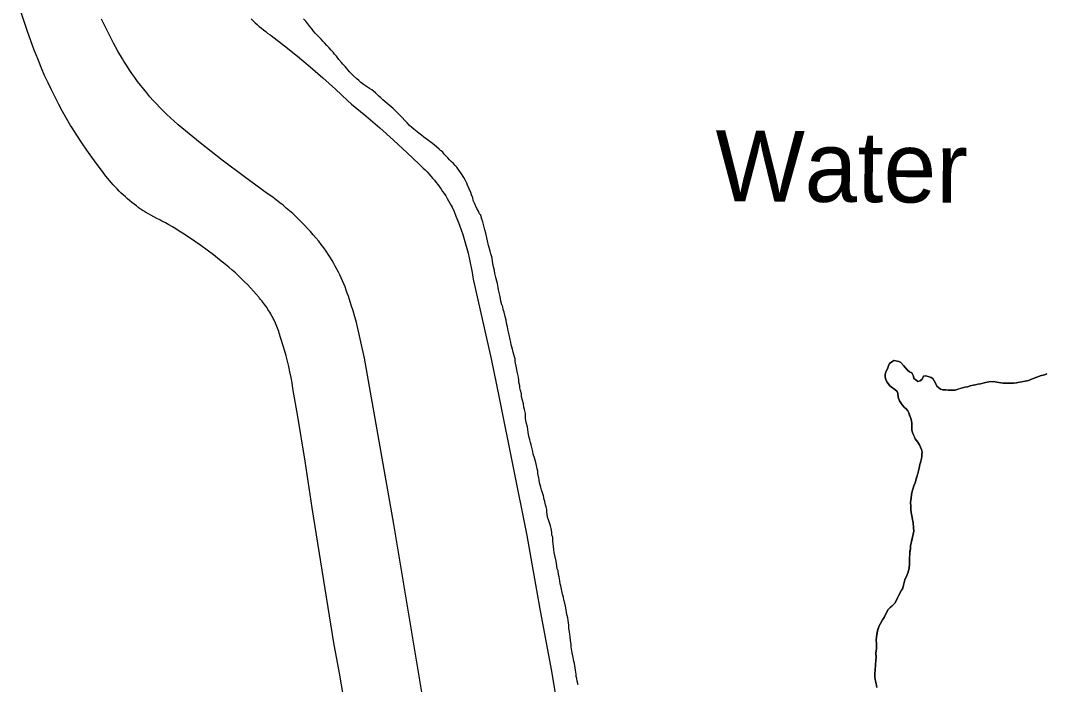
# Model space of a CAD drawing. Extents: x 3172297 to 3210190, y 958463 to 983887.
# Drawn here: x 3188661 to 3190110, y 970542 to 971480 of the extents above; entities that cross this region are included whole.
import ezdxf

# ---------------------------------------------------------------- set-up
doc = ezdxf.new("R2010")
doc.units = 0
for name, color, linetype in [('V-LEVE-TOET', 7, 'Continuous'), ('V-RIVR-IDEN', 7, 'Continuous'), ('V-ROAD-CNTR', 7, 'Continuous'), ('V-SITE-VEGE', 7, 'Continuous'), ('V-TOPO-SHOR', 7, 'Continuous')]:
    doc.layers.add(name, color=color, linetype=linetype)

msp = doc.modelspace()

# ---------------------------------------------------------------- linework, layer by layer
at = {"layer": 'V-LEVE-TOET'}
for points in [[(3188950.3, 971135.2), (3188950.3, 971135.2), (3188941.8, 971142.1), (3188933.1, 971148.9), (3188924.3, 971155.5), (3188915.4, 971162), (3188906.4, 971168.3), (3188897.3, 971174.4), (3188889.3, 971179.6), (3188889.3, 971179.6), (3188884.5, 971182.7), (3188879.8, 971185.6), (3188875, 971188.5), (3188870.1, 971191.3), (3188865.2, 971194.1), (3188860.3, 971196.8), (3188857.3, 971198.4), (3188857.3, 971198.4), (3188853.1, 971200.6), (3188848.9, 971202.8), (3188844.8, 971205.1), (3188841.5, 971207), (3188841.5, 971207), (3188840.1, 971207.6), (3188838.8, 971208.3), (3188837.5, 971209), (3188836.2, 971209.8), (3188835, 971210.6), (3188833.7, 971211.3), (3188832.4, 971212.1), (3188831.2, 971213), (3188830, 971213.8), (3188828.8, 971214.7), (3188827.6, 971215.6), (3188826.4, 971216.5), (3188825.2, 971217.4), (3188824.2, 971218.2), (3188824.2, 971218.2), (3188821, 971220.7), (3188817.9, 971223.2), (3188814.7, 971225.7), (3188811.7, 971228.3), (3188808.7, 971230.9), (3188805.7, 971233.7), (3188802.8, 971236.4), (3188799.9, 971239.2), (3188797.1, 971242.1), (3188794.3, 971245), (3188791.5, 971247.9), (3188788.9, 971250.9), (3188786.2, 971254), (3188783.7, 971257.1), (3188781.2, 971260.2), (3188778.7, 971263.4), (3188776.3, 971266.6), (3188776.2, 971266.7), (3188776.2, 971266.7), (3188768.7, 971276.7), (3188761.3, 971286.9), (3188754.1, 971297.1), (3188747, 971307.5), (3188740.1, 971318), (3188733.4, 971328.6), (3188731.3, 971332), (3188731.3, 971332), (3188725.6, 971341.8), (3188720, 971351.7), (3188714.6, 971361.7), (3188709.3, 971371.8), (3188704.2, 971382), (3188699.4, 971392.2), (3188694.6, 971402.6), (3188690.1, 971413), (3188685.8, 971423.5), (3188681.6, 971434.1), (3188680, 971438.3), (3188680, 971438.3), (3188670, 971466.2), (3188660.6, 971494.4)], [(3188986.2, 971482.4), (3188989, 971479.6), (3188991.9, 971477), (3188994.8, 971474.4), (3188997.7, 971471.8), (3189000.8, 971469.3), (3189003.8, 971466.8), (3189006.9, 971464.4), (3189010, 971462), (3189013.2, 971459.7), (3189014.5, 971458.8), (3189014.5, 971458.8), (3189033.2, 971444.3), (3189051.6, 971429.6), (3189069.8, 971414.5), (3189087.6, 971399.1), (3189105.3, 971383.3), (3189122.6, 971367.3), (3189128.1, 971362.1), (3189128.1, 971362.1), (3189148.2, 971345.4), (3189168.1, 971328.3), (3189187.6, 971310.9), (3189206.9, 971293.1), (3189223.6, 971277.2), (3189223.6, 971277.2), (3189226.5, 971274.5), (3189229.3, 971271.7), (3189232, 971269), (3189234.7, 971266.1), (3189237.4, 971263.3), (3189240, 971260.4), (3189242.6, 971257.4), (3189245.1, 971254.4), (3189247.5, 971251.3), (3189249.9, 971248.2), (3189252.3, 971245.1), (3189254.6, 971241.9), (3189256.8, 971238.7), (3189259, 971235.5), (3189261.1, 971232.2), (3189263.2, 971228.8), (3189265.2, 971225.5), (3189267.1, 971222.1), (3189269, 971218.7), (3189270.2, 971216.4), (3189270.2, 971216.4), (3189273, 971210.1), (3189275.6, 971203.7), (3189278.1, 971197.3), (3189280.6, 971190.8), (3189282.9, 971184.3), (3189285.1, 971177.8), (3189287.2, 971171.2), (3189289.1, 971164.6), (3189291, 971158), (3189292.7, 971151.3)], [(3189292.7, 971151.3), (3189294.3, 971144.6), (3189295.8, 971137.9), (3189297.2, 971131.1), (3189298.5, 971124.3), (3189299.6, 971117.5), (3189300, 971114.8), (3189300, 971114.8), (3189325.1, 971002.3), (3189336.7, 970947.2), (3189336.7, 970947.2), (3189375.9, 970752.6), (3189375.9, 970752.6), (3189393.5, 970651.1), (3189410.2, 970562.9), (3189410.2, 970562.9), (3189444.3, 970359.5)], [(3189125, 970475.7), (3189111, 970557.8), (3189103.1, 970600.6), (3189103.1, 970600.6), (3189072.6, 970791.6), (3189072.6, 970791.6), (3189062.8, 970857.5), (3189051.8, 970923.2), (3189046.6, 970952.3), (3189046.6, 970952.3), (3189045.4, 970960.2), (3189044.1, 970968), (3189042.7, 970975.7), (3189041.1, 970983.5), (3189039.4, 970991.2), (3189037.6, 970998.9), (3189035.6, 971006.5), (3189033.5, 971014.2), (3189031.2, 971021.7), (3189028.9, 971029.3), (3189027.4, 971033.7), (3189027.4, 971033.7), (3189026.7, 971036.1), (3189026, 971038.5), (3189025.2, 971040.8), (3189024.4, 971043.2), (3189023.5, 971045.5), (3189022.6, 971047.8), (3189021.6, 971050.1), (3189020.7, 971052.4), (3189019.6, 971054.7), (3189018.6, 971056.9), (3189017.5, 971059.1), (3189016.3, 971061.3), (3189015.1, 971063.5), (3189013.9, 971065.7), (3189012.7, 971067.8), (3189011.4, 971069.9), (3189010, 971072), (3189008.7, 971074.1), (3189007.3, 971076.2), (3189005.8, 971078.2), (3189004.4, 971080.2), (3189002.9, 971082.2), (3189001.3, 971084.1), (3188999.7, 971086), (3188998.1, 971087.9), (3188997.5, 971088.7), (3188997.5, 971088.7), (3188993.6, 971093.3), (3188989.6, 971097.8), (3188985.5, 971102.3), (3188981.4, 971106.6), (3188977.1, 971111), (3188972.8, 971115.2), (3188968.5, 971119.4), (3188964, 971123.4), (3188959.5, 971127.5), (3188954.9, 971131.4), (3188950.3, 971135.2)]]:
    msp.add_lwpolyline(points, dxfattribs=at)
at = {"layer": 'V-ROAD-CNTR'}
for points in [[(3189146.3, 971003), (3189135.3, 971053.3), (3189132.9, 971061.6), (3189130.4, 971069.8), (3189127.8, 971078), (3189125, 971086.1), (3189125, 971086.1), (3189123.6, 971090.5), (3189122.1, 971094.9), (3189120.5, 971099.2), (3189118.9, 971103.6), (3189117.1, 971107.9), (3189115.3, 971112.1), (3189113.5, 971116.4), (3189111.5, 971120.6), (3189109.5, 971124.7), (3189107.4, 971128.9), (3189105.2, 971133), (3189103, 971137), (3189100.7, 971141), (3189098.3, 971145), (3189095.8, 971148.9), (3189093.3, 971152.8), (3189092.5, 971154), (3189092.5, 971154), (3189089, 971158.8), (3189085.4, 971163.6), (3189081.7, 971168.3), (3189077.9, 971172.9), (3189074.1, 971177.4), (3189070.1, 971181.9), (3189066.1, 971186.3), (3189062.1, 971190.7), (3189057.9, 971194.9), (3189053.7, 971199.1), (3189049.4, 971203.2), (3189045, 971207.3), (3189040.5, 971211.3), (3189036, 971215.2), (3189031.4, 971219), (3189026.8, 971222.7), (3189022.1, 971226.3), (3189017.3, 971229.9), (3189012.5, 971233.4), (3189009.1, 971235.7), (3189009.1, 971235.7), (3188977.1, 971259.1), (3188945.4, 971283), (3188914.2, 971307.5), (3188883.4, 971332.5), (3188882.6, 971333.2), (3188877.4, 971337.8), (3188872.3, 971342.5), (3188867.3, 971347.3), (3188862.3, 971352.2), (3188857.5, 971357.1), (3188852.7, 971362.2), (3188848, 971367.3), (3188843.4, 971372.5), (3188839, 971377.8), (3188834.6, 971383.2), (3188830.2, 971388.6), (3188826, 971394.1), (3188821.9, 971399.7), (3188817.9, 971405.4), (3188814, 971411.1), (3188810.2, 971416.9), (3188806.5, 971422.8), (3188804.5, 971425.9), (3188804.5, 971425.9), (3188798.2, 971437), (3188792.1, 971448.1), (3188786.1, 971459.4), (3188780.4, 971470.8), (3188774.8, 971482.2)], [(3189387, 969592.5), (3189378.6, 969645.9), (3189378.6, 969645.9), (3189335.3, 969888.2), (3189305.1, 970072.7), (3189305.1, 970072.7), (3189239.6, 970457.8), (3189239.6, 970457.8), (3189188, 970768.6), (3189188, 970768.6), (3189146.3, 971003)]]:
    msp.add_lwpolyline(points, dxfattribs=at)
at = {"layer": 'V-SITE-VEGE'}
for p, q in [((3189888, 970995.6), (3189886.4, 970992)), ((3189891.3, 970997.9), (3189888, 970995.6)), ((3189894, 970999.7), (3189891.3, 970997.9)), ((3189901.2, 970998.4), (3189894, 970999.7)), ((3189903.9, 970996.9), (3189901.2, 970998.4)), ((3189907.5, 970992.7), (3189903.9, 970996.9)), ((3189882.8, 970983.9), (3189881.8, 970980)), ((3189881.8, 970980), (3189881.8, 970976.1)), ((3189885.2, 970987.8), (3189882.8, 970983.9)), ((3189886.4, 970992), (3189885.2, 970987.8)), ((3189910.4, 970989.6), (3189907.5, 970992.7)), ((3189913.4, 970986.3), (3189910.4, 970989.6)), ((3189916.4, 970983.8), (3189913.4, 970986.3)), ((3189919.4, 970982.3), (3189916.4, 970983.8)), ((3189922, 970977.5), (3189919.4, 970982.3)), ((3190110.4, 970980.8), (3190106.7, 970979.6)), ((3189881.8, 970976.1), (3189882.6, 970973.1)), ((3189882.6, 970973.1), (3189884.1, 970969.5)), ((3189884.1, 970969.5), (3189885.9, 970967.1)), ((3189885.9, 970967.1), (3189888.5, 970963.7)), ((3189922.3, 970974.5), (3189922, 970977.5)), ((3189925, 970972.6), (3189922.3, 970974.5)), ((3189928.2, 970970.2), (3189925, 970972.6)), ((3189931.3, 970970.8), (3189928.2, 970970.2)), ((3189934.3, 970973.4), (3189931.3, 970970.8)), ((3189936.1, 970977.6), (3189934.3, 970973.4)), ((3189939.4, 970977.9), (3189936.1, 970977.6)), ((3189942.7, 970977.2), (3189939.4, 970977.9)), ((3189946.6, 970975.7), (3189942.7, 970977.2)), ((3189949.3, 970974.2), (3189946.6, 970975.7)), ((3189952.8, 970967.5), (3189949.3, 970974.2)), ((3189954.6, 970963.3), (3189952.8, 970967.5)), ((3190009.3, 970965.4), (3190006, 970964.8)), ((3190012.6, 970966.3), (3190009.3, 970965.4)), ((3190016.5, 970966.8), (3190012.6, 970966.3)), ((3190023.4, 970968.5), (3190016.5, 970966.8)), ((3190031.2, 970970), (3190023.4, 970968.5)), ((3190034, 970969.6), (3190031.2, 970970)), ((3190034.9, 970969.9), (3190034, 970969.6)), ((3190039.7, 970969.3), (3190034.9, 970969.9)), ((3190045, 970968), (3190039.7, 970969.3)), ((3190048.3, 970967.7), (3190045, 970968)), ((3190063.1, 970967.5), (3190048.3, 970967.7)), ((3190067.3, 970968), (3190063.1, 970967.5)), ((3190079.6, 970970.3), (3190067.3, 970968)), ((3190084.4, 970971.5), (3190079.6, 970970.3)), ((3190090.8, 970974.4), (3190084.4, 970971.5)), ((3190097.7, 970976.7), (3190090.8, 970974.4)), ((3190101, 970978.2), (3190097.7, 970976.7)), ((3190106.7, 970979.6), (3190101, 970978.2)), ((3189888.5, 970963.7), (3189895.4, 970958.9)), ((3189895.4, 970958.9), (3189898.7, 970956.1)), ((3189898.7, 970956.1), (3189899.5, 970953.1)), ((3189899.5, 970953.1), (3189900.1, 970947.7)), ((3189960, 970959.3), (3189954.6, 970963.3)), ((3189963.3, 970958.4), (3189960, 970959.3)), ((3189967.5, 970958.4), (3189963.3, 970958.4)), ((3189971, 970957.7), (3189967.5, 970958.4)), ((3189977.7, 970957.9), (3189971, 970957.7)), ((3189980.7, 970957.9), (3189977.7, 970957.9)), ((3189990.9, 970961.1), (3189980.7, 970957.9)), ((3189994.5, 970962), (3189990.9, 970961.1)), ((3189998.1, 970962.5), (3189994.5, 970962)), ((3190002.1, 970964), (3189998.1, 970962.5)), ((3190006, 970964.8), (3190002.1, 970964)), ((3189900.1, 970947.7), (3189902.1, 970942.9)), ((3189902.1, 970942.9), (3189905.7, 970937.1)), ((3189905.7, 970937.1), (3189909.2, 970933.2)), ((3189909.2, 970933.2), (3189911.6, 970931.3)), ((3189911.6, 970931.3), (3189913.7, 970928.6)), ((3189913.7, 970928.6), (3189915.1, 970925.6)), ((3189915.1, 970925.6), (3189918.6, 970916.3)), ((3189918.6, 970916.3), (3189919.5, 970911.7)), ((3189919.5, 970911.7), (3189919.7, 970908.4)), ((3189919.7, 970908.4), (3189919.7, 970901.2)), ((3189919.7, 970901.2), (3189921.1, 970896.4)), ((3189921.1, 970896.4), (3189924, 970889.2)), ((3189924, 970889.2), (3189928.2, 970884.3)), ((3189928.2, 970884.3), (3189930.2, 970880.7)), ((3189930.2, 970880.7), (3189933.2, 970874.1)), ((3189933.4, 970864.1), (3189933, 970861.1)), ((3189933.2, 970874.1), (3189934, 970870.1)), ((3189934, 970870.1), (3189933.4, 970867.1)), ((3189933.4, 970867.1), (3189933.4, 970864.1)), ((3189930.2, 970849.8), (3189929.9, 970847.7)), ((3189930.5, 970850.7), (3189930.2, 970849.8)), ((3189931.2, 970854.2), (3189930.5, 970850.7)), ((3189933, 970861.1), (3189931.2, 970854.2)), ((3189928.9, 970843.8), (3189924.2, 970827)), ((3189929.9, 970847.7), (3189928.9, 970843.8)), ((3189922.4, 970822.5), (3189919.9, 970814.4)), ((3189924.2, 970827), (3189922.4, 970822.5)), ((3189918.9, 970810.2), (3189918.6, 970805.1)), ((3189919.9, 970814.4), (3189918.9, 970810.2)), ((3189918.6, 970805.1), (3189917.6, 970799.1)), ((3189917.6, 970799.1), (3189918.2, 970793.7)), ((3189918.2, 970793.7), (3189918.1, 970789.2)), ((3189918.1, 970789.2), (3189918.4, 970785)), ((3189918.4, 970785), (3189921.2, 970770.3)), ((3189921.2, 970770.3), (3189921.7, 970763.7)), ((3189921.7, 970763.7), (3189922.3, 970758.8)), ((3189922.3, 970758.8), (3189919.1, 970743.6)), ((3189919.1, 970743.6), (3189917.5, 970738.5)), ((3189917.5, 970738.5), (3189917.5, 970733.4)), ((3189916.4, 970719.9), (3189916.1, 970715.1)), ((3189916.5, 970728.6), (3189916.4, 970719.9)), ((3189917.5, 970733.4), (3189916.5, 970728.6)), ((3189915.7, 970706.7), (3189914.1, 970700.4)), ((3189916, 970712.1), (3189915.7, 970706.7)), ((3189916.1, 970715.1), (3189916, 970712.1)), ((3189912.6, 970695.9), (3189909.8, 970689.9)), ((3189914.1, 970700.4), (3189912.6, 970695.9)), ((3189906.7, 970677.9), (3189904.8, 970675.3)), ((3189907.6, 970682.1), (3189906.7, 970677.9)), ((3189908.9, 970686), (3189907.6, 970682.1)), ((3189909.8, 970689.9), (3189908.9, 970686)), ((3189899.3, 970664.2), (3189895.9, 970657.3)), ((3189899.6, 970665.1), (3189899.3, 970664.2)), ((3189900.8, 970667.2), (3189899.6, 970665.1)), ((3189904.8, 970675.3), (3189900.8, 970667.2)), ((3189885.6, 970647.2), (3189880.4, 970636.5)), ((3189888.9, 970650.5), (3189885.6, 970647.2)), ((3189891.4, 970652.6), (3189888.9, 970650.5)), ((3189893.8, 970655), (3189891.4, 970652.6)), ((3189895.9, 970657.3), (3189893.8, 970655)), ((3189878.2, 970633.2), (3189875.2, 970628.1)), ((3189880.4, 970636.5), (3189878.2, 970633.2)), ((3189870.8, 970617.7), (3189869.5, 970608.7)), ((3189873.3, 970624.6), (3189870.8, 970617.7)), ((3189875.2, 970628.1), (3189873.3, 970624.6)), ((3189869.5, 970608.7), (3189869.2, 970604.5)), ((3189869.2, 970604.5), (3189869.7, 970600)), ((3189869.4, 970592.8), (3189868.7, 970586.2)), ((3189869.7, 970600), (3189869.4, 970592.8)), ((3189868.6, 970576.9), (3189868.2, 970569.4)), ((3189868.9, 970579.9), (3189868.6, 970576.9)), ((3189868.7, 970586.2), (3189868.9, 970579.9)), ((3189867.5, 970562.5), (3189867.2, 970556.8)), ((3189868.2, 970569.4), (3189867.5, 970562.5)), ((3189867.2, 970556.8), (3189867.4, 970552.2)), ((3189867.4, 970552.2), (3189868, 970546.8)), ((3189868, 970546.8), (3189869.1, 970543.2)), ((3189869.1, 970543.2), (3189870.3, 970537.8))]:
    msp.add_line(p, q, dxfattribs=at)
at = {"layer": 'V-TOPO-SHOR'}
for points in [[(3189074.4, 971465.1), (3189072.3, 971467.8), (3189069.3, 971471.7), (3189066.4, 971475.4), (3189063.4, 971479), (3189060.1, 971482.3)], [(3189325.8, 971147.5), (3189324.9, 971150.5), (3189323.8, 971154.2), (3189322.3, 971159.3), (3189321.7, 971162.3), (3189320.3, 971168.9), (3189319.2, 971173.1), (3189317.7, 971179.7), (3189316.6, 971184.6), (3189315.4, 971188.2), (3189314.3, 971192.1), (3189313.4, 971195.7), (3189312, 971199.6), (3189310.5, 971204.5), (3189310.5, 971205.1), (3189309, 971207.2), (3189307.3, 971210.8), (3189305.2, 971214.7), (3189302, 971222), (3189299.9, 971225.9), (3189299.4, 971229.5), (3189297.6, 971233.7), (3189296.5, 971237), (3189294.4, 971242.5), (3189292.1, 971247.6), (3189290.9, 971250.3), (3189290.3, 971251.2), (3189288.5, 971254.8), (3189286.5, 971258.2), (3189283.2, 971263.6), (3189281.2, 971266.6), (3189278.5, 971270.3), (3189276.7, 971273), (3189274.4, 971275.4), (3189272, 971277.9), (3189269, 971280.9), (3189266.3, 971283.3), (3189264, 971286.1), (3189261.3, 971288.8), (3189258.9, 971291.2), (3189257.1, 971293.9), (3189254.8, 971295.8), (3189253.6, 971296.7), (3189252.1, 971298.2), (3189248.2, 971301.8), (3189245.5, 971304), (3189242.3, 971306.4), (3189239.3, 971308.6), (3189236.6, 971310.7), (3189233.6, 971312.8), (3189230.4, 971315.3), (3189226.8, 971318), (3189223.2, 971321), (3189216.1, 971326.5), (3189213.4, 971329), (3189210.1, 971331.7), (3189206.6, 971335.6), (3189203.3, 971339), (3189199.4, 971343.2), (3189196.2, 971346.3), (3189193.5, 971349), (3189190.2, 971352.3), (3189187, 971355.7), (3189184.3, 971358.1), (3189181.3, 971360.6), (3189178.3, 971362.7), (3189172.1, 971368.2), (3189169.4, 971370.9), (3189166.7, 971373.3), (3189164.4, 971375.5), (3189162, 971377.9), (3189159.3, 971380.3), (3189156.9, 971382.2), (3189153.3, 971384.3), (3189150.7, 971386.1), (3189147.7, 971388), (3189145, 971389.8), (3189141.4, 971392.5), (3189138.2, 971395.6), (3189135.5, 971397.7), (3189130.7, 971402), (3189128.3, 971404.4), (3189125.4, 971407.4), (3189123.3, 971410.2), (3189120.9, 971412.6), (3189118.9, 971415), (3189115.6, 971418.4), (3189113.8, 971420.8), (3189110.3, 971425), (3189106.7, 971429.6), (3189104, 971432.6), (3189102, 971435.3), (3189099.3, 971438.1), (3189096.3, 971441.4), (3189093.4, 971445), (3189090.1, 971448.4), (3189087.4, 971451.1), (3189085.1, 971453.8), (3189080, 971459), (3189076.7, 971462.3), (3189074.4, 971465.1)], [(3189419.9, 970702.3), (3189418.7, 970705.3), (3189418.2, 970709.8), (3189417.6, 970713.1), (3189417.1, 970716.2), (3189415.4, 970724.3), (3189414.5, 970728.2), (3189413.9, 970732.4), (3189413.4, 970737.5), (3189412.6, 970744.4), (3189412.3, 970749.5), (3189411.2, 970753.2), (3189410.9, 970757.1), (3189410.1, 970762.5), (3189408.9, 970766.1), (3189406.3, 970774.8), (3189405.1, 970778.4), (3189404, 970786.3), (3189403.8, 970789.3), (3189403.2, 970792.9), (3189402.3, 970795.9), (3189401.2, 970800.4), (3189400.3, 970803.4), (3189399.2, 970808.5), (3189398, 970812.5), (3189396.6, 970817), (3189395.4, 970820.6), (3189393.7, 970826.9), (3189393.1, 970831.1), (3189392.6, 970834.1), (3189391.1, 970840.2), (3189391.1, 970841.7), (3189391.2, 970843.5), (3189390.3, 970846.8), (3189389.4, 970851.3), (3189388.3, 970855.8), (3189387.4, 970858.8), (3189386.3, 970862.4), (3189384.8, 970867.6), (3189384, 970871.2), (3189382.8, 970876.9), (3189381.7, 970880.5), (3189381.1, 970883.8), (3189379.9, 970887.7), (3189378.8, 970890.8), (3189377.9, 970895), (3189377.4, 970898.3), (3189377.1, 970902.2), (3189376.5, 970905.8), (3189375.4, 970910.6), (3189374.5, 970914.8), (3189374, 970918.4), (3189373.7, 970924.8), (3189372.6, 970930.5), (3189371.7, 970933.8), (3189370.9, 970938.6), (3189369.2, 970944.9), (3189368.3, 970949.4), (3189368.1, 970952.4), (3189366.9, 970957.3), (3189366, 970960.9), (3189365.8, 970963.9), (3189364.6, 970969), (3189364.4, 970972), (3189363.8, 970976.2), (3189362.4, 970981.6), (3189361.3, 970989.2), (3189359.3, 970998.2), (3189359, 971002.1), (3189358.1, 971005.1), (3189356.4, 971011.7), (3189355.5, 971015.7), (3189353.8, 971022), (3189353, 971025.6), (3189352.1, 971029.2), (3189350.7, 971035.8), (3189349.5, 971041.8), (3189348.4, 971047.3), (3189347.2, 971052.4), (3189346.4, 971056.9), (3189345.2, 971061.7), (3189343.5, 971068), (3189342.4, 971071.7), (3189341.8, 971075.6), (3189340.6, 971078.6), (3189339.2, 971083.4), (3189338.6, 971086.7), (3189338.1, 971090), (3189336.9, 971093.9), (3189335.8, 971099.7), (3189335.2, 971102.7), (3189334.1, 971108.4), (3189333.2, 971111.7), (3189331.7, 971116.8), (3189330.6, 971122.5), (3189329.8, 971126.8), (3189328.6, 971132.2), (3189327.8, 971136.7), (3189327.2, 971140.3), (3189326.6, 971144.2), (3189325.8, 971147.5)], [(3189917.5, 970738.5), (3189919.1, 970743.6), (3189919.7, 970746.9), (3189920.4, 970749.9), (3189922.3, 970758.8), (3189921.7, 970763.7), (3189921.2, 970770.3), (3189918.4, 970785), (3189918.1, 970789.2), (3189918.2, 970793.7), (3189917.6, 970799.1), (3189918.6, 970805.1), (3189918.9, 970810.2), (3189919.9, 970814.4), (3189922.4, 970822.5), (3189924.2, 970827), (3189925.8, 970832.7), (3189927.4, 970838.4), (3189928.9, 970843.8), (3189929.9, 970847.7), (3189930.2, 970849.8), (3189930.5, 970850.7), (3189931.2, 970854.2), (3189932.1, 970857.5), (3189933, 970861.1), (3189933.4, 970864.1), (3189933.4, 970867.1), (3189934, 970870.1), (3189933.2, 970874), (3189930.2, 970880.7), (3189928.2, 970884.3), (3189926.1, 970886.7), (3189924, 970889.2), (3189922.6, 970892.8), (3189921.1, 970896.4), (3189919.7, 970901.2), (3189919.7, 970904.2), (3189919.7, 970908.4), (3189919.5, 970911.7), (3189918.6, 970916.3), (3189917.5, 970919.3), (3189916.3, 970922.6), (3189915.1, 970925.6), (3189913.7, 970928.6), (3189911.6, 970931.3), (3189909.2, 970933.2), (3189905.7, 970937.1), (3189902.1, 970942.9), (3189900.1, 970947.7), (3189899.5, 970953.1), (3189898.7, 970956.1), (3189895.4, 970958.9), (3189892.4, 970961), (3189888.5, 970963.7), (3189885.9, 970967.1), (3189884.1, 970969.5), (3189882.6, 970973.1), (3189881.8, 970976.1), (3189881.8, 970980), (3189882.8, 970983.9), (3189885.2, 970987.8), (3189886.4, 970992), (3189888, 970995.6), (3189891.3, 970997.9), (3189894, 970999.7), (3189897.6, 970999.1), (3189901.2, 970998.4), (3189903.9, 970996.9), (3189907.5, 970992.7), (3189910.4, 970989.6), (3189913.4, 970986.3), (3189916.4, 970983.8), (3189919.4, 970982.3), (3189922, 970977.5), (3189922.3, 970974.5), (3189925, 970972.6), (3189928.2, 970970.2), (3189931.3, 970970.8), (3189934.3, 970973.4), (3189936.1, 970977.6), (3189939.4, 970977.9), (3189942.7, 970977.2), (3189946.6, 970975.7), (3189949.3, 970974.2), (3189951.1, 970970.8), (3189952.8, 970967.5), (3189954.6, 970963.3), (3189957, 970961.5), (3189960, 970959.3), (3189963.3, 970958.4), (3189967.5, 970958.4), (3189971, 970957.7), (3189977.7, 970957.9), (3189980.7, 970957.9), (3189986.1, 970959.6), (3189990.9, 970961.1), (3189994.5, 970962), (3189998.1, 970962.5), (3190002.1, 970964), (3190006, 970964.8), (3190009.3, 970965.4)], [(3190009.3, 970965.4), (3190012.6, 970966.3), (3190016.5, 970966.8), (3190019.8, 970967.7), (3190023.4, 970968.5), (3190028.2, 970969.4), (3190031.2, 970970), (3190034, 970969.6), (3190034.9, 970969.9), (3190039.7, 970969.3), (3190045, 970968), (3190048.3, 970967.7), (3190053.4, 970967.6), (3190059.5, 970967.5), (3190063.1, 970967.5), (3190067.3, 970968), (3190071.8, 970968.9), (3190079.6, 970970.3), (3190084.4, 970971.5), (3190090.8, 970974.4), (3190097.7, 970976.7), (3190101, 970978.2), (3190106.7, 970979.6), (3190110.4, 970980.8)], [(3189870.3, 970537.8), (3189869.1, 970543.2), (3189868, 970546.8), (3189867.4, 970552.2), (3189867.2, 970556.8), (3189867.5, 970562.5), (3189868.2, 970569.4), (3189868.6, 970576.9), (3189868.9, 970579.9), (3189868.7, 970586.2), (3189869.4, 970592.8), (3189869.7, 970600), (3189869.2, 970604.5), (3189869.5, 970608.7), (3189870.2, 970613.2), (3189870.8, 970617.7), (3189871.5, 970619.5), (3189873.3, 970624.6), (3189875.2, 970628.1), (3189878.2, 970633.2), (3189880.4, 970636.5), (3189885.6, 970647.2), (3189888.9, 970650.5), (3189891.4, 970652.6), (3189893.8, 970655), (3189895.9, 970657.3), (3189899.3, 970664.2), (3189899.6, 970665.1), (3189900.8, 970667.2), (3189904.8, 970675.3), (3189906, 970677), (3189906.7, 970677.9), (3189907.6, 970682.1), (3189908.9, 970686), (3189909.8, 970689.9), (3189912.6, 970695.9), (3189914.1, 970700.4), (3189915.7, 970706.7), (3189916.1, 970712.1), (3189916.1, 970715.1), (3189916.4, 970719.9), (3189916.5, 970726.5), (3189916.5, 970728.6), (3189916.9, 970730.4), (3189917.5, 970733.4), (3189917.5, 970738.5)], [(3189448.4, 970541.6), (3189447, 970546.7), (3189446.1, 970550.4), (3189445.6, 970553.4), (3189445.3, 970556.4), (3189444.5, 970562.1), (3189443.9, 970565.4), (3189442.8, 970571.7), (3189442.2, 970575), (3189440.8, 970582.5), (3189439.9, 970586.8), (3189438.5, 970595.2), (3189438.3, 970598.5), (3189437.4, 970604.5), (3189436.9, 970609), (3189436.3, 970613.5), (3189435.2, 970621.3), (3189435, 970625.6), (3189434.4, 970629.2), (3189434.1, 970632.2), (3189433.6, 970636.1), (3189432.7, 970639.4), (3189431.9, 970643.6), (3189431.3, 970647.5), (3189430.2, 970652.6), (3189429.3, 970656.9), (3189428.2, 970661.4), (3189427.3, 970665.3), (3189426.2, 970669.5), (3189425.3, 970674.3), (3189423.6, 970681.2), (3189423, 970684.3), (3189422.2, 970688.2), (3189421.9, 970691.2), (3189421.3, 970694.2), (3189420.5, 970697.2), (3189419.9, 970702.3)]]:
    msp.add_lwpolyline(points, dxfattribs=at)

# ---------------------------------------------------------------- texts
at = {"layer": 'V-RIVR-IDEN'}
msp.add_text('Water', height=100, rotation=359.5938, dxfattribs=at).set_placement((3189641.6, 971225))

doc.saveas('drawing.dxf')
